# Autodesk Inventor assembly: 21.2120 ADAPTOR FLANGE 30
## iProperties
Created: 2012-10
Part Number: 21.2120 ADAPTOR FLANGE 30
Document SubType Name: Assembly
Designer: Administrator
Author: Administrator
